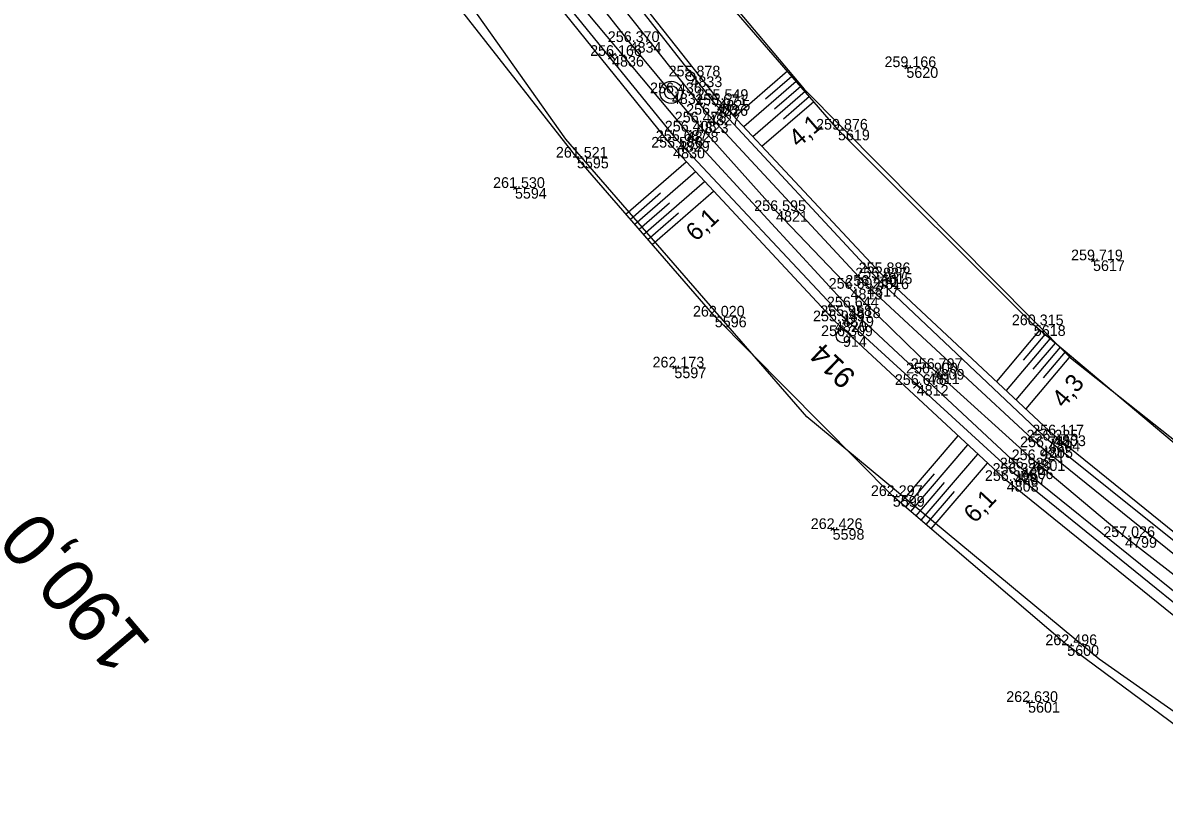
# Model space of a CAD drawing. Extents: x -809970 to -809480, y -1011362 to -1010672.
# Drawn here: x -809839.9 to -809711.9, y -1011200.2 to -1011112.9 of the extents above; entities that cross this region are included whole.
import ezdxf

# ---------------------------------------------------------------- set-up
doc = ezdxf.new("R2010")
doc.units = 0
for name, color, linetype in [('Vrstva 1', 7, 'Continuous'), ('Vrstva 4', 7, 'Continuous'), ('Vrstva 48', 7, 'Continuous'), ('Vrstva 49', 7, 'Continuous'), ('Vrstva 53', 7, 'Continuous'), ('Vrstva 60', 7, 'Continuous'), ('Vrstva 61', 7, 'Continuous'), ('Vrstva 63', 7, 'Continuous'), ('Vrstva 7', 7, 'Continuous')]:
    doc.layers.add(name, color=color, linetype=linetype)

msp = doc.modelspace()

# ---------------------------------------------------------------- linework, layer by layer
at = {"layer": 'Vrstva 1'}
msp.add_lwpolyline([(-809704.48, -1011179.77), (-809716.3, -1011170.61), (-809726.57, -1011161.99), (-809737.88, -1011151.76), (-809747.09, -1011142.76), (-809755.44, -1011134.04), (-809764.34, -1011124.1), (-809767.12, -1011120.83), (-809771.86, -1011115.08), (-809777.01, -1011108.56), (-809781.91, -1011102.09), (-809787, -1011095.02), (-809791.76, -1011088.08), (-809799.73, -1011075.77), (-809806.84, -1011063.8), (-809813.58, -1011051.4), (-809820, -1011038.37), (-809825.44, -1011026.1)], dxfattribs=at)
at = {"layer": 'Vrstva 4'}
for points in [[(-809514.07, -1011276.67), (-809539.83, -1011264.26), (-809562.29, -1011253.6), (-809585.06, -1011242.59), (-809604.03, -1011233.74), (-809622.75, -1011224.34), (-809635.98, -1011217.78), (-809658.04, -1011205.96), (-809678.21, -1011194.44), (-809694.3, -1011183.84), (-809703.86, -1011176.66), (-809724.9, -1011159.78), (-809744.11, -1011141.6), (-809762.15, -1011122.16), (-809774.57, -1011106.33), (-809789.63, -1011085.97), (-809801.28, -1011067.08), (-809811.54, -1011048.02), (-809817.16, -1011036.69), (-809823.08, -1011022.98)], [(-809514.73, -1011277.55), (-809539.87, -1011265.31), (-809562.72, -1011254.42), (-809585.31, -1011243.69), (-809604.51, -1011234.26), (-809623.3, -1011225.16), (-809636.52, -1011218.94), (-809659.57, -1011206.8), (-809678.11, -1011195.78), (-809694.14, -1011185.08), (-809704.56, -1011177.6), (-809725.72, -1011160.53), (-809745.22, -1011142.43), (-809763.07, -1011123.23), (-809775.62, -1011107.42), (-809790.76, -1011086.7), (-809802.43, -1011068.09), (-809812.88, -1011048.59), (-809818.37, -1011037.45), (-809824.5, -1011023.86)], [(-809517.34, -1011281.17), (-809542.25, -1011268.91), (-809565.05, -1011257.74), (-809585.85, -1011248.03), (-809606.19, -1011237.96), (-809624.44, -1011229.46), (-809639.03, -1011221.78), (-809662.37, -1011209.59), (-809679.75, -1011199.24), (-809695.35, -1011189.16), (-809706.37, -1011181.63), (-809728.71, -1011163.52), (-809748.04, -1011145.82), (-809766.46, -1011126.18), (-809779.35, -1011110.29), (-809779.4, -1011110.26), (-809794.33, -1011089.31), (-809806.51, -1011070.34), (-809817.46, -1011050.77), (-809822.78, -1011039.81), (-809827.65, -1011029.26)], [(-809516.72, -1011279.86), (-809541.72, -1011267.84), (-809564.36, -1011257.13), (-809585.64, -1011247.05), (-809605.96, -1011237.21), (-809624.35, -1011228.4), (-809638.66, -1011221.38), (-809661.97, -1011208.93), (-809679.17, -1011198.73), (-809694.94, -1011188.71), (-809705.67, -1011180.87), (-809727.9, -1011162.91), (-809747.29, -1011144.85), (-809765.46, -1011125.12), (-809778.44, -1011109.55), (-809793.36, -1011088.57), (-809805.27, -1011069.6), (-809816.07, -1011050.21), (-809821.49, -1011039.16), (-809826.21, -1011028.82)]]:
    msp.add_lwpolyline(points, dxfattribs=at)
at = {"layer": 'Vrstva 48'}
for p, q in [((-809754.15, -1011118.37), (-809760.09, -1011123.51)), ((-809753.17, -1011119.51), (-809759.07, -1011124.6)), ((-809753.66, -1011118.94), (-809756.62, -1011121.5)), ((-809752.19, -1011120.64), (-809758.04, -1011125.7)), ((-809752.68, -1011120.07), (-809755.62, -1011122.61)), ((-809751.21, -1011121.78), (-809757.02, -1011126.8)), ((-809751.7, -1011121.21), (-809754.61, -1011123.73)), ((-809772.27, -1011134.39), (-809765.51, -1011128.52)), ((-809771.29, -1011135.52), (-809764.48, -1011129.62)), ((-809770.31, -1011136.66), (-809763.46, -1011130.72)), ((-809771.78, -1011134.96), (-809768.39, -1011132.01)), ((-809769.33, -1011137.79), (-809762.44, -1011131.82)), ((-809770.8, -1011136.09), (-809767.39, -1011133.13)), ((-809769.82, -1011137.22), (-809766.38, -1011134.24)), ((-809725.89, -1011147.4), (-809730.73, -1011153.17)), ((-809724.74, -1011148.37), (-809729.64, -1011154.19)), ((-809725.31, -1011147.89), (-809727.75, -1011150.78)), ((-809724.16, -1011148.85), (-809726.63, -1011151.78)), ((-809723.59, -1011149.33), (-809728.54, -1011155.22)), ((-809723.02, -1011149.82), (-809725.5, -1011152.77)), ((-809722.44, -1011150.3), (-809727.44, -1011156.24)), ((-809741.46, -1011166.78), (-809735.02, -1011159.25)), ((-809740.32, -1011167.75), (-809733.92, -1011160.27)), ((-809739.18, -1011168.73), (-809732.82, -1011161.3)), ((-809738.04, -1011169.7), (-809731.72, -1011162.32)), ((-809740.89, -1011167.27), (-809737.68, -1011163.52)), ((-809739.74, -1011168.24), (-809736.56, -1011164.51)), ((-809738.6, -1011169.22), (-809735.44, -1011165.51))]:
    msp.add_line(p, q, dxfattribs=at)
at = {"layer": 'Vrstva 49'}
for p, q in [((-809741, -1011117.73), (-809740.65, -1011118.08)), ((-809741, -1011118.08), (-809740.65, -1011117.73)), ((-809784.9, -1011131.28), (-809784.55, -1011131.63)), ((-809784.9, -1011131.63), (-809784.55, -1011131.28)), ((-809720.08, -1011139.4), (-809719.73, -1011139.75)), ((-809720.08, -1011139.75), (-809719.73, -1011139.4)), ((-809767.02, -1011151.41), (-809766.66, -1011151.76)), ((-809767.02, -1011151.76), (-809766.66, -1011151.41)), ((-809749.28, -1011169.53), (-809748.92, -1011169.88)), ((-809749.28, -1011169.88), (-809748.92, -1011169.53)), ((-809727.36, -1011188.94), (-809727.01, -1011189.29)), ((-809727.36, -1011189.29), (-809727.01, -1011188.94))]:
    msp.add_line(p, q, dxfattribs=at)
for points in [[(-809511.61, -1011271.23), (-809536.39, -1011258.33), (-809560.01, -1011246.27), (-809576.21, -1011238.32), (-809612.21, -1011219.9), (-809615.12, -1011217.12), (-809615.79, -1011215.73), (-809619.54, -1011223.55), (-809624.01, -1011221.32), (-809620.33, -1011213.39), (-809626.47, -1011211.63), (-809636.4, -1011208.19), (-809641.71, -1011205.47), (-809669.15, -1011190.8), (-809699.73, -1011169.4), (-809726.54, -1011146.85), (-809748.5, -1011124.91), (-809769.57, -1011100.55), (-809784.98, -1011078.51), (-809794.37, -1011063.91), (-809798.01, -1011059.09), (-809806.77, -1011045.25), (-809814.25, -1011034.46), (-809820.96, -1011021.87)], [(-809703.94, -1011175.69), (-809724.27, -1011159.21), (-809743.72, -1011141.01), (-809761.9, -1011121.58), (-809774.23, -1011105.94), (-809788.4, -1011086.61), (-809800.65, -1011066.76), (-809811.15, -1011047.78), (-809816.63, -1011036.45), (-809822.75, -1011022.84)], [(-809702.86, -1011197.5), (-809722.79, -1011182.74), (-809742.35, -1011166.01), (-809762.31, -1011145.88), (-809777.77, -1011128.05), (-809796.68, -1011103.89), (-809805.3, -1011085.56), (-809812.13, -1011072.97), (-809818.26, -1011061.48), (-809829.17, -1011039.9), (-809831.46, -1011030.92)], [(-809517.95, -1011282.18), (-809542.49, -1011269.58), (-809565.63, -1011258.32), (-809585.98, -1011248.4), (-809606.44, -1011238.24), (-809621.62, -1011231.05), (-809624.45, -1011230.4), (-809627.73, -1011228.86), (-809639.59, -1011222.81), (-809662.84, -1011211.14), (-809680.58, -1011200.68), (-809695.92, -1011190.37), (-809707.33, -1011182.3), (-809729.57, -1011164.32), (-809748.84, -1011146.41), (-809766.98, -1011126.93), (-809779.99, -1011110.78), (-809794.75, -1011089.67), (-809807.08, -1011070.6), (-809818.27, -1011051.22), (-809824.25, -1011040.29), (-809829.11, -1011030.23)]]:
    msp.add_lwpolyline(points, dxfattribs=at)
at = {"layer": 'Vrstva 53'}
for points in [[(-809817.83, -1011024.91), (-809805.06, -1011048.21), (-809777.13, -1011090.84), (-809773.31, -1011095.41), (-809752.3, -1011120.38), (-809722.41, -1011150.52), (-809685.06, -1011180.11), (-809638.61, -1011207.44), (-809624.45, -1011211.08), (-809620, -1011212.86), (-809615.56, -1011215.28), (-809614.76, -1011215.85), (-809598.39, -1011227.55), (-809488.36, -1011283.38)], [(-809479.96, -1011306.98), (-809541.53, -1011278.39), (-809624.88, -1011241.51), (-809627.72, -1011240.25), (-809632.39, -1011238.49), (-809632.72, -1011238.43), (-809644.97, -1011236.14), (-809685.42, -1011208.04), (-809719.22, -1011184.3), (-809751.99, -1011157.11), (-809779.01, -1011125.97), (-809796.54, -1011101.19), (-809810.89, -1011076.81), (-809836.26, -1011028.53)]]:
    msp.add_lwpolyline(points, dxfattribs=at)
at = {"layer": 'Vrstva 60'}
for p, q in [((-809771.86, -1011115.08), (-809771.86, -1011115.08)), ((-809773.83, -1011116.64), (-809773.83, -1011116.64)), ((-809740.83, -1011117.9), (-809740.83, -1011117.9)), ((-809765.04, -1011118.94), (-809765.04, -1011118.94)), ((-809767.12, -1011120.83), (-809767.12, -1011120.83)), ((-809761.9, -1011121.58), (-809761.9, -1011121.58)), ((-809763.07, -1011123.23), (-809763.07, -1011123.23)), ((-809762.15, -1011122.16), (-809762.15, -1011122.16)), ((-809764.34, -1011124.1), (-809764.34, -1011124.1)), ((-809765.46, -1011125.12), (-809765.46, -1011125.12)), ((-809748.5, -1011124.91), (-809748.5, -1011124.91)), ((-809766.98, -1011126.93), (-809766.98, -1011126.93)), ((-809766.46, -1011126.18), (-809766.46, -1011126.18)), ((-809777.77, -1011128.05), (-809777.77, -1011128.05)), ((-809784.72, -1011131.45), (-809784.72, -1011131.45)), ((-809755.44, -1011134.04), (-809755.44, -1011134.04)), ((-809719.9, -1011139.57), (-809719.9, -1011139.57)), ((-809743.72, -1011141.01), (-809743.72, -1011141.01)), ((-809745.22, -1011142.43), (-809745.22, -1011142.43)), ((-809744.11, -1011141.6), (-809744.11, -1011141.6)), ((-809747.09, -1011142.76), (-809747.09, -1011142.76)), ((-809747.29, -1011144.85), (-809747.29, -1011144.85)), ((-809762.31, -1011145.88), (-809762.31, -1011145.88)), ((-809748.04, -1011145.82), (-809748.04, -1011145.82)), ((-809748.84, -1011146.41), (-809748.84, -1011146.41)), ((-809726.54, -1011146.85), (-809726.54, -1011146.85)), ((-809747.94, -1011148.07), (-809747.94, -1011148.07)), ((-809766.84, -1011151.59), (-809766.84, -1011151.59)), ((-809738.42, -1011152.26), (-809738.42, -1011152.26)), ((-809737.88, -1011151.76), (-809737.88, -1011151.76)), ((-809739.67, -1011153.55), (-809739.67, -1011153.55)), ((-809724.9, -1011159.78), (-809724.9, -1011159.78)), ((-809724.27, -1011159.21), (-809724.27, -1011159.21)), ((-809725.72, -1011160.53), (-809725.72, -1011160.53)), ((-809727.9, -1011162.91), (-809727.9, -1011162.91)), ((-809726.57, -1011161.99), (-809726.57, -1011161.99)), ((-809729.57, -1011164.32), (-809729.57, -1011164.32)), ((-809728.71, -1011163.52), (-809728.71, -1011163.52)), ((-809742.35, -1011166.01), (-809742.35, -1011166.01)), ((-809749.1, -1011169.71), (-809749.1, -1011169.71)), ((-809716.3, -1011170.61), (-809716.3, -1011170.61)), ((-809722.79, -1011182.74), (-809722.79, -1011182.74)), ((-809727.18, -1011189.11), (-809727.18, -1011189.11))]:
    msp.add_line(p, q, dxfattribs=at)
at = {"layer": 'Vrstva 63'}
msp.add_line((-809747.9, -1011148.11), (-809747.97, -1011148.04), dxfattribs=at)
msp.add_circle((-809747.94, -1011148.07), 0.756, dxfattribs=at)
at = {"layer": 'Vrstva 7'}
for p, q in [((-809774.23, -1011116.95), (-809773.44, -1011116.33)), ((-809773.52, -1011117.03), (-809774.14, -1011116.25)), ((-809765.07, -1011118.91), (-809765, -1011118.98)), ((-809740.02, -1011153.91), (-809739.32, -1011153.19)), ((-809739.31, -1011153.9), (-809740.02, -1011153.2))]:
    msp.add_line(p, q, dxfattribs=at)
for centre, radius in [((-809767.2, -1011120.73), 1.25), ((-809765.04, -1011118.94), 0.5), ((-809767.2, -1011120.73), 0.752)]:
    msp.add_circle(centre, radius, dxfattribs=at)

# ---------------------------------------------------------------- texts
at = {"layer": 'Vrstva 48'}
for s, rotation, p in [('4,1', 40.8557, (-809752.94, -1011127)), ('6,1', 42.975, (-809764.43, -1011137.54)), ('4,3', 49.937, (-809723.17, -1011156.24)), ('6,1', 47.1006, (-809733.14, -1011169.15))]:
    msp.add_text(s, height=2, rotation=rotation, dxfattribs=at).set_placement(p)
at = {"layer": 'Vrstva 60'}
for s, p in [('4834', (-809771.86, -1011116.28)), ('4836', (-809773.83, -1011117.84)), ('5620', (-809740.83, -1011119.1)), ('4833', (-809765.04, -1011120.14)), ('4831', (-809767.12, -1011122.03)), ('4825', (-809761.9, -1011122.78)), ('4827', (-809763.07, -1011124.43)), ('4826', (-809762.15, -1011123.36)), ('4823', (-809764.34, -1011125.3)), ('4828', (-809765.46, -1011126.32)), ('5619', (-809748.5, -1011126.11)), ('4830', (-809766.98, -1011128.13)), ('4829', (-809766.46, -1011127.38)), ('5595', (-809777.77, -1011129.25)), ('5594', (-809784.72, -1011132.65)), ('4821', (-809755.44, -1011135.24)), ('5617', (-809719.9, -1011140.77)), ('4815', (-809743.72, -1011142.21)), ('4817', (-809745.22, -1011143.63)), ('4816', (-809744.11, -1011142.8)), ('4813', (-809747.09, -1011143.96)), ('4818', (-809747.29, -1011146.05)), ('5596', (-809762.31, -1011147.08)), ('4820', (-809748.84, -1011147.61)), ('4819', (-809748.04, -1011147.02)), ('5618', (-809726.54, -1011148.05)), ('914', (-809747.94, -1011149.27)), ('5597', (-809766.84, -1011152.79)), ('4811', (-809738.42, -1011153.46)), ('4809', (-809737.88, -1011152.96)), ('4812', (-809739.67, -1011154.75)), ('4803', (-809724.27, -1011160.41)), ('4804', (-809724.9, -1011160.98)), ('4805', (-809725.72, -1011161.73)), ('4806', (-809727.9, -1011164.11)), ('4801', (-809726.57, -1011163.19)), ('4808', (-809729.57, -1011165.52)), ('4807', (-809728.71, -1011164.72)), ('5599', (-809742.35, -1011167.21)), ('5598', (-809749.1, -1011170.91)), ('4799', (-809716.3, -1011171.81)), ('5600', (-809722.79, -1011183.94)), ('5601', (-809727.18, -1011190.31))]:
    msp.add_text(s, height=1.2, dxfattribs=at).set_placement(p)
at = {"layer": 'Vrstva 61'}
for s, p in [('256.370', (-809774.31, -1011115.08)), ('256.166', (-809776.29, -1011116.64)), ('259.166', (-809743.28, -1011117.9)), ('255.878', (-809767.49, -1011118.94)), ('256.436', (-809769.57, -1011120.83)), ('255.549', (-809764.35, -1011121.58)), ('256.303', (-809765.52, -1011123.23)), ('255.671', (-809764.51, -1011122.16)), ('256.478', (-809766.8, -1011124.1)), ('256.408', (-809767.92, -1011125.12)), ('259.876', (-809750.95, -1011124.91)), ('255.586', (-809769.44, -1011126.93)), ('255.687', (-809768.92, -1011126.18)), ('261.521', (-809780.13, -1011128.05)), ('261.530', (-809787.17, -1011131.45)), ('256.595', (-809757.89, -1011134.04)), ('259.719', (-809722.36, -1011139.57)), ('255.886', (-809746.18, -1011141.01)), ('256.450', (-809747.67, -1011142.43)), ('255.837', (-809746.56, -1011141.6)), ('256.692', (-809749.54, -1011142.76)), ('256.644', (-809749.74, -1011144.85)), ('262.020', (-809764.76, -1011145.88)), ('255.958', (-809750.49, -1011145.82)), ('255.949', (-809751.3, -1011146.41)), ('260.315', (-809729, -1011146.85)), ('256.309', (-809750.39, -1011148.07)), ('262.173', (-809769.29, -1011151.59)), ('256.900', (-809740.87, -1011152.26)), ('256.797', (-809740.33, -1011151.76)), ('256.676', (-809742.12, -1011153.55)), ('256.225', (-809727.36, -1011159.78)), ('256.117', (-809726.72, -1011159.21)), ('256.741', (-809728.08, -1011160.53)), ('256.928', (-809730.35, -1011162.91)), ('256.924', (-809729.02, -1011161.99)), ('256.326', (-809731.16, -1011163.52)), ('256.305', (-809732.02, -1011164.32)), ('262.297', (-809744.81, -1011166.01)), ('262.426', (-809751.55, -1011169.71)), ('257.026', (-809718.75, -1011170.61)), ('262.496', (-809725.24, -1011182.74)), ('262.630', (-809729.63, -1011189.11))]:
    msp.add_text(s, height=1.2, dxfattribs=at).set_placement(p)
at = {"layer": 'Vrstva 63'}
msp.add_text('914', height=2.4, rotation=135.6701, dxfattribs=at).set_placement((-809746.35, -1011152.44))
at = {"layer": 'Vrstva 7'}
msp.add_text('190,0', height=6, rotation=130.3493, dxfattribs=at).set_placement((-809825.33, -1011182.61))

doc.saveas('drawing.dxf')
